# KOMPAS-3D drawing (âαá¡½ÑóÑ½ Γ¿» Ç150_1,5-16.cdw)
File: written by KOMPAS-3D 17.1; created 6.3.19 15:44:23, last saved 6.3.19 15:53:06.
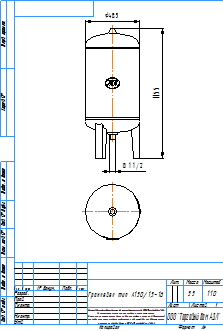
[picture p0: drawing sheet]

Sheet 1: A4, portrait

Title block, sheet 1: name: Гранлевел тип А150/1,5-16; material: Сталь 10  ГОСТ 1050-88; mass: 55; sheets: 1; sheet format: A4; stored path: C:\Users\kka\KOMPAS_Work\!Trash\ГРАНЛЕВЕЛ тип А Расширительный бак\KOMPAS 2D\Гранлевел тип А150_1,5-16.cdw

Views: Вид 1, Проекционный вид 2
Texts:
  kka
  adl
  Рама для чертежей
  Лит-Масса-Масштаб
  Материал-Предприятие
  Масштаб
  Изм.
  Лист
  № докум.
  Подп.
  Дата
  Лит.
  Разраб.
  Пров.
  Т.контр.
  Листов
  Внимание! Данный продукт является объектом авторского права ООО «Торговый Дом АДЛ».
  Запрещается изменение, копирование, распространение
  (в том числе путем копирования на другие сайты и ресурсы в Интернете)
  или любое иное использование информации и объектов без предварительного
  согласия правообладателя (ООО «Торговый Дом АДЛ»).
  Н.контр.
  Утв.
  ООО "Торговый дом АДЛ"
  Изменение
  Номер документа
  Подпись
  Обозначение документа
  Наименование изделия
  Масса изделия по ГОСТ 2.109-73
  Порядковый номер листа
  Общее количество листов в документе
  Характер работы, выполненной лицом, подписавшим документ
  Наименование или индекс предприятия, выпускающего документ
  Инв. № подл.
  Подп. и дата
  Взам. инв. №
  Инв. № дубл.
  Инвентарный номер подлинника по ГОСТ 2.501-68
  Подпись принявшего подлинник в отдел технической документации
  Инвентарный номер подлинника, взамен которого выпущен данный подлинник
  Инвентарный номер дубликата по ГОСТ 2.502-68
  Подпись принявшего дубликат в отдел технической документации
  Справ. №
  Перв. примен.
  Обозначение документа, взамен или на основании которого выпущен данный документ
  Обозначение документа, в котором впервые записан данный документ
  Подпись лица, копировавшего чертеж
  Обозначение формата листа
  !Рама для чертежа
Dimensions and other numbers on the sheet: 1155; 485; 1 1/2; 1:10; 1; 55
